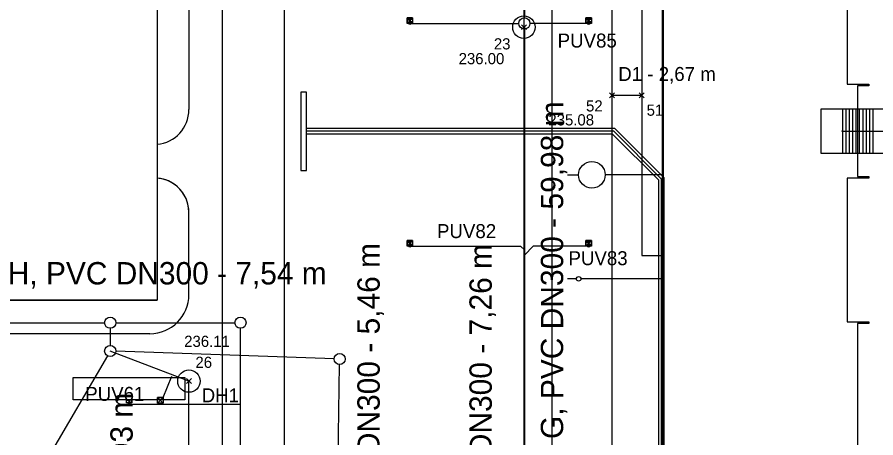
# Model space of a CAD drawing. Extents: x -264234 to -263604, y -1242346 to -1242049.
# Drawn here: x -263972 to -263895.1, y -1242191.8 to -1242154.2 of the extents above; entities that cross this region are included whole.
import ezdxf

# ---------------------------------------------------------------- set-up
doc = ezdxf.new("R2010")
doc.units = 0
for name, color, linetype in [('KFA_BODY_CISLO', 7, 'Continuous'), ('KFA_BODY_SYMBOL', 7, 'Continuous'), ('KFA_BODY_VYSKA', 7, 'Continuous'), ('KFA_DAZDOVA_KANALIZACIA_pripojky_tA_tC', 7, 'Continuous'), ('KFA_DAZDOVA_KANALIZACIA_pripojky_tA_tC_popis', 7, 'Continuous'), ('KFA_DAZDOVA_KANALIZACIA_vetva_G', 7, 'Continuous'), ('KFA_DAZDOVA_KANALIZACIA_vetva_G_popis', 7, 'Continuous'), ('KFA_DAZDOVA_KANALIZACIA_vetva_H', 7, 'Continuous'), ('KFA_DAZDOVA_KANALIZACIA_vetva_H_popis', 7, 'Continuous'), ('KFA_JESTV_IS_DSP_-_KANAL_DAZD', 7, 'Continuous'), ('KFA_SITUACIA_DSP', 7, 'Continuous'), ('KFA_SO_40-2-II_DK_PRIPOJKY_UV_PROJEKT', 7, 'Continuous'), ('KFA_SO_40-2-II_DK_PRIPOJKY_UV_PROJEKT_popis', 7, 'Continuous'), ('KFA_SO_40-2-II_DK_UV_PROJEKT', 7, 'Continuous')]:
    doc.layers.add(name, color=color, linetype=linetype)

msp = doc.modelspace()

# ---------------------------------------------------------------- linework, layer by layer
at = {"layer": 'KFA_BODY_SYMBOL'}
for p, q in [((-263926.86, -1242155.303), (-263926.418, -1242154.861)), ((-263926.418, -1242155.303), (-263926.86, -1242154.861)), ((-263918.984, -1242161.403), (-263918.542, -1242160.961)), ((-263918.542, -1242161.403), (-263918.984, -1242160.961)), ((-263916.314, -1242161.403), (-263915.872, -1242160.961)), ((-263915.872, -1242161.403), (-263916.314, -1242160.961)), ((-263956.837, -1242186.94), (-263956.395, -1242186.498)), ((-263956.395, -1242186.94), (-263956.837, -1242186.498))]:
    msp.add_line(p, q, dxfattribs=at)
at = {"layer": 'KFA_DAZDOVA_KANALIZACIA_pripojky_tA_tC'}
msp.add_line((-263916.093, -1242161.182), (-263918.763, -1242161.182), dxfattribs=at)
at = {"layer": 'KFA_DAZDOVA_KANALIZACIA_vetva_G'}
msp.add_lwpolyline([(-263926.523, -1242108.42), (-263926.639, -1242155.082), (-263926.646, -1242205.066)], dxfattribs=at)
msp.add_circle((-263926.639, -1242155.082), 1, dxfattribs=at)
at = {"layer": 'KFA_DAZDOVA_KANALIZACIA_vetva_H'}
msp.add_lwpolyline([(-263956.104, -1242251.541), (-263956.553, -1242222.652), (-263956.616, -1242186.719), (-263963.661, -1242184.028)], dxfattribs=at)
msp.add_circle((-263956.616, -1242186.719), 1, dxfattribs=at)
at = {"layer": 'KFA_JESTV_IS_DSP_-_KANAL_DAZD'}
for p, q in [((-263918.764, -1242152.564), (-263918.757, -1242196.225)), ((-263943.628, -1242184.728), (-263963.161, -1242184.046)), ((-263963.914, -1242184.46), (-263969.615, -1242194.201)), ((-263943.946, -1242236.311), (-263943.136, -1242185.245))]:
    msp.add_line(p, q, dxfattribs=at)
for centre in [(-263963.661, -1242184.028), (-263943.128, -1242184.745)]:
    msp.add_circle(centre, 0.5, dxfattribs=at)
at = {"layer": 'KFA_SITUACIA_DSP'}
for p, q in [((-263959.468, -1242059.534), (-263959.468, -1242179.482)), ((-263924.143, -1242082.64), (-263924.143, -1242185.14)), ((-263948.093, -1242087.901), (-263948.093, -1242241.458)), ((-263953.617, -1242244.458), (-263953.617, -1242093.307)), ((-263926.593, -1242107.902), (-263926.593, -1242154.252)), ((-263926.593, -1242107.902), (-263926.593, -1242154.252)), ((-263956.618, -1242127.418), (-263956.618, -1242162.449)), ((-263914.218, -1242196.332), (-263914.218, -1242132.432)), ((-263897.693, -1242147.332), (-263897.693, -1242160.182)), ((-263937.093, -1242154.652), (-263937.093, -1242154.362)), ((-263937.093, -1242154.362), (-263936.593, -1242154.362)), ((-263936.593, -1242154.652), (-263937.093, -1242154.362)), ((-263936.593, -1242154.652), (-263937.093, -1242154.362)), ((-263937.093, -1242154.362), (-263937.093, -1242154.652)), ((-263936.593, -1242154.652), (-263937.093, -1242154.652)), ((-263937.093, -1242154.652), (-263936.593, -1242154.652)), ((-263936.743, -1242154.752), (-263927.093, -1242154.752)), ((-263936.593, -1242154.362), (-263936.593, -1242154.652)), ((-263920.944, -1242154.752), (-263926.093, -1242154.752)), ((-263921.093, -1242154.652), (-263921.093, -1242154.362)), ((-263921.093, -1242154.362), (-263920.593, -1242154.362)), ((-263920.593, -1242154.652), (-263921.093, -1242154.362)), ((-263920.593, -1242154.652), (-263921.093, -1242154.362)), ((-263921.093, -1242154.362), (-263921.093, -1242154.652)), ((-263920.593, -1242154.652), (-263921.093, -1242154.652)), ((-263921.093, -1242154.652), (-263920.593, -1242154.652)), ((-263920.593, -1242154.362), (-263920.593, -1242154.652)), ((-263926.593, -1242155.252), (-263926.593, -1242204.252)), ((-263897.693, -1242160.182), (-263895.768, -1242160.182)), ((-263895.768, -1242160.332), (-263896.768, -1242160.332)), ((-263896.768, -1242160.332), (-263896.768, -1242168.432)), ((-263895.768, -1242160.182), (-263895.768, -1242160.332)), ((-263916.093, -1242161.182), (-263918.763, -1242161.182)), ((-263898.118, -1242162.382), (-263898.118, -1242166.382)), ((-263897.818, -1242162.382), (-263897.818, -1242166.382)), ((-263897.518, -1242162.382), (-263897.518, -1242166.382)), ((-263897.218, -1242162.382), (-263897.218, -1242166.382)), ((-263896.918, -1242162.382), (-263896.918, -1242166.382)), ((-263896.618, -1242162.382), (-263896.618, -1242166.382)), ((-263896.318, -1242162.382), (-263896.318, -1242166.382)), ((-263896.018, -1242162.382), (-263896.018, -1242166.382)), ((-263895.718, -1242162.382), (-263895.718, -1242166.382)), ((-263895.418, -1242162.382), (-263895.418, -1242166.382)), ((-263918.489, -1242164.132), (-263946.093, -1242164.132)), ((-263918.593, -1242164.382), (-263946.093, -1242164.382)), ((-263918.696, -1242164.632), (-263946.093, -1242164.632)), ((-263898.118, -1242164.382), (-263893.618, -1242164.382)), ((-263959.468, -1242165.549), (-263959.468, -1242165.549)), ((-263959.467, -1242168.582), (-263959.467, -1242168.582)), ((-263922.745, -1242168.282), (-263921.745, -1242168.282)), ((-263914.143, -1242168.282), (-263919.355, -1242168.282)), ((-263895.768, -1242168.582), (-263897.693, -1242168.582)), ((-263897.693, -1242168.582), (-263897.693, -1242181.432)), ((-263896.768, -1242168.432), (-263895.768, -1242168.432)), ((-263895.768, -1242168.432), (-263895.768, -1242168.582)), ((-263956.618, -1242178.982), (-263956.618, -1242171.645)), ((-263937.093, -1242174.553), (-263937.093, -1242174.263)), ((-263937.093, -1242174.263), (-263936.593, -1242174.263)), ((-263936.593, -1242174.553), (-263937.093, -1242174.263)), ((-263936.593, -1242174.553), (-263937.093, -1242174.263)), ((-263937.093, -1242174.263), (-263937.093, -1242174.553)), ((-263936.593, -1242174.553), (-263937.093, -1242174.553)), ((-263937.093, -1242174.553), (-263936.593, -1242174.553)), ((-263936.743, -1242174.653), (-263926.953, -1242174.653)), ((-263936.593, -1242174.263), (-263936.593, -1242174.553)), ((-263926.953, -1242174.653), (-263926.593, -1242174.978)), ((-263925.798, -1242174.653), (-263926.593, -1242175.448)), ((-263920.944, -1242174.653), (-263925.798, -1242174.653)), ((-263921.093, -1242174.553), (-263921.093, -1242174.263)), ((-263921.093, -1242174.263), (-263920.593, -1242174.263)), ((-263920.593, -1242174.553), (-263921.093, -1242174.263)), ((-263920.593, -1242174.553), (-263921.093, -1242174.263)), ((-263921.093, -1242174.263), (-263921.093, -1242174.553)), ((-263920.593, -1242174.553), (-263921.093, -1242174.553)), ((-263921.093, -1242174.553), (-263920.593, -1242174.553)), ((-263920.593, -1242174.263), (-263920.593, -1242174.553)), ((-263921.938, -1242177.582), (-263922.738, -1242177.582)), ((-263915.293, -1242177.582), (-263921.538, -1242177.582)), ((-263914.143, -1242177.582), (-263915.293, -1242177.582)), ((-264131.568, -1242179.482), (-263959.468, -1242179.482)), ((-263959.468, -1242179.482), (-264131.568, -1242179.482)), ((-263959.468, -1242179.482), (-264077.23, -1242179.482)), ((-263956.618, -1242178.982), (-263956.618, -1242178.982)), ((-264013.161, -1242181.5), (-263964.161, -1242181.5)), ((-263963.161, -1242181.5), (-263952.5, -1242181.5)), ((-263897.693, -1242181.432), (-263895.768, -1242181.432)), ((-263895.768, -1242181.582), (-263896.768, -1242181.582)), ((-263896.768, -1242181.582), (-263896.768, -1242203.332)), ((-263895.768, -1242181.432), (-263895.768, -1242181.582)), ((-263960.118, -1242182.482), (-264034.158, -1242182.482)), ((-263963.661, -1242182), (-263963.661, -1242183.528)), ((-263952, -1242222.527), (-263952, -1242182)), ((-263924.143, -1242185.14), (-263924.143, -1242250.14)), ((-263962.218, -1242188.382), (-263961.718, -1242188.382)), ((-263962.218, -1242188.672), (-263962.218, -1242188.382)), ((-263962.218, -1242188.382), (-263961.718, -1242188.672)), ((-263962.218, -1242188.382), (-263961.718, -1242188.672)), ((-263961.718, -1242188.382), (-263962.218, -1242188.382)), ((-263961.718, -1242188.672), (-263962.218, -1242188.672)), ((-263961.718, -1242188.382), (-263961.718, -1242188.672)), ((-263961.718, -1242188.672), (-263961.718, -1242188.382)), ((-263961.868, -1242188.772), (-263952, -1242188.772))]:
    msp.add_line(p, q, dxfattribs=at)
for points in [[(-263794.893, -1242227.382), (-263808.968, -1242241.457), (-263894.968, -1242241.457), (-263909.043, -1242227.382), (-263909.043, -1242196.333), (-263914.143, -1242196.333), (-263914.143, -1242132.433), (-263909.043, -1242132.433), (-263909.043, -1242101.382), (-263894.968, -1242087.307), (-263808.968, -1242087.307), (-263794.893, -1242101.382), (-263794.893, -1242227.382)], [(-263918.489, -1242164.132), (-263914.1, -1242168.521), (-263914.1, -1242199.486), (-263910.004, -1242203.582), (-263891.768, -1242203.582)], [(-263918.696, -1242164.632), (-263914.6, -1242168.728), (-263914.6, -1242199.693), (-263910.211, -1242204.082), (-263891.768, -1242204.082)], [(-263918.593, -1242164.382), (-263914.35, -1242168.625), (-263914.35, -1242199.59), (-263910.108, -1242203.832), (-263891.768, -1242203.832)], [(-263956.618, -1242178.982), (-263956.618, -1242171.626), (-263956.64, -1242171.257), (-263956.707, -1242170.894), (-263956.87, -1242170.411), (-263957.158, -1242169.893), (-263957.435, -1242169.549), (-263957.705, -1242169.291), (-263958.077, -1242169.024), (-263958.45, -1242168.829), (-263958.842, -1242168.69), (-263959.056, -1242168.638), (-263959.273, -1242168.601), (-263959.468, -1242168.582)]]:
    msp.add_lwpolyline(points, dxfattribs=at)
for points in [[(-263893.618, -1242118.282), (-263916.093, -1242118.282), (-263916.093, -1242175.482), (-263914.293, -1242175.482), (-263914.293, -1242210.482), (-263893.618, -1242210.482), (-263893.618, -1242166.382), (-263900.043, -1242166.382), (-263900.043, -1242162.382), (-263893.618, -1242162.382)], [(-263946.093, -1242167.882), (-263946.093, -1242160.882), (-263946.593, -1242160.882), (-263946.593, -1242167.882)], [(-263966.968, -1242186.382), (-263956.968, -1242186.382), (-263956.968, -1242188.382), (-263966.968, -1242188.382)]]:
    msp.add_lwpolyline(points, close=True, dxfattribs=at)
for centre, radius in [((-263936.843, -1242154.752), 0.1), ((-263926.593, -1242154.752), 0.5), ((-263920.844, -1242154.752), 0.1), ((-263898.118, -1242164.382), 0.05), ((-263920.55, -1242168.282), 1.195), ((-263936.843, -1242174.653), 0.1), ((-263920.844, -1242174.653), 0.1), ((-263921.738, -1242177.582), 0.2), ((-263963.661, -1242181.5), 0.5), ((-263952, -1242181.5), 0.5), ((-263961.968, -1242188.772), 0.1)]:
    msp.add_circle(centre, radius, dxfattribs=at)
for centre, radius, start, end in [((-263959.738, -1242162.441), 3.12, 274.96374, 359.8482), ((-263959.668, -1242171.626), 3.05, 359.64411, 86.21555), ((-263960.118, -1242178.982), 3.5, 270, 0)]:
    msp.add_arc(centre, radius, start, end, dxfattribs=at)
at = {"layer": 'KFA_SO_40-2-II_DK_PRIPOJKY_UV_PROJEKT'}
for points in [[(-263936.743, -1242154.752), (-263927.093, -1242154.752)], [(-263920.944, -1242154.752), (-263926.093, -1242154.752)], [(-263936.743, -1242174.653), (-263926.953, -1242174.653), (-263926.593, -1242174.978)], [(-263920.944, -1242174.653), (-263925.798, -1242174.653), (-263926.593, -1242175.448)], [(-263958.93, -1242188.19), (-263958.149, -1242186.27)]]:
    msp.add_lwpolyline(points, dxfattribs=at)
at = {"layer": 'KFA_SO_40-2-II_DK_UV_PROJEKT'}
for points in [[(-263937.093, -1242154.757), (-263937.093, -1242154.257), (-263936.593, -1242154.257), (-263936.593, -1242154.757), (-263937.093, -1242154.757), (-263936.593, -1242154.257), (-263937.093, -1242154.257), (-263936.593, -1242154.757)], [(-263921.093, -1242154.757), (-263921.093, -1242154.257), (-263920.593, -1242154.257), (-263920.593, -1242154.757), (-263921.093, -1242154.757), (-263920.593, -1242154.257), (-263921.093, -1242154.257), (-263920.593, -1242154.757)], [(-263937.093, -1242174.658), (-263937.093, -1242174.158), (-263936.593, -1242174.158), (-263936.593, -1242174.658), (-263937.093, -1242174.658), (-263936.593, -1242174.158), (-263937.093, -1242174.158), (-263936.593, -1242174.658)], [(-263921.093, -1242174.658), (-263921.093, -1242174.158), (-263920.593, -1242174.158), (-263920.593, -1242174.658), (-263921.093, -1242174.658), (-263920.593, -1242174.158), (-263921.093, -1242174.158), (-263920.593, -1242174.658)], [(-263959.43, -1242188.69), (-263959.43, -1242188.19), (-263958.93, -1242188.19), (-263958.93, -1242188.69), (-263959.43, -1242188.69), (-263958.93, -1242188.19), (-263959.43, -1242188.19), (-263958.93, -1242188.69)]]:
    msp.add_lwpolyline(points, dxfattribs=at)

# ---------------------------------------------------------------- texts
at = {"layer": 'KFA_BODY_CISLO'}
for s, p in [('23', (-263929.324, -1242157.075)), ('52', (-263921.077, -1242162.619)), ('51', (-263915.653, -1242163.002)), ('26', (-263956.034, -1242185.539))]:
    msp.add_text(s, height=1, dxfattribs=at).set_placement(p)
at = {"layer": 'KFA_BODY_VYSKA'}
for s, p in [('236.00', (-263932.48, -1242158.395)), ('235.08', (-263924.447, -1242163.868)), ('236.11', (-263957.04, -1242183.663))]:
    msp.add_text(s, height=1, dxfattribs=at).set_placement(p)
at = {"layer": 'KFA_DAZDOVA_KANALIZACIA_pripojky_tA_tC_popis'}
msp.add_text('D1 - 2,67 m', height=1.25, dxfattribs=at).set_placement((-263918.194, -1242159.893))
at = {"layer": 'KFA_DAZDOVA_KANALIZACIA_vetva_G_popis'}
for s, p in [('G, PVC DN300 - 59,98 m', (-263923.121, -1242191.895)), ('G, PVC DN300 - 5,46 m', (-263939.541, -1242203.058)), ('G, PVC DN300 - 7,26 m', (-263929.511, -1242203.15))]:
    msp.add_text(s, height=2, rotation=90, dxfattribs=at).set_placement(p)
at = {"layer": 'KFA_DAZDOVA_KANALIZACIA_vetva_H_popis'}
for s, rotation, p in [('H, PVC DN300 - 7,54 m', 360, (-263972.826, -1242178.078)), ('H, PVC DN300 - 35,93 m', 90, (-263961.646, -1242217.779))]:
    msp.add_text(s, height=2, rotation=rotation, dxfattribs=at).set_placement(p)
msp.add_text('DH1', height=1.25, dxfattribs=at).set_placement((-263955.474, -1242188.614))
at = {"layer": 'KFA_SO_40-2-II_DK_PRIPOJKY_UV_PROJEKT_popis'}
for s, p in [('PUV85', (-263923.618, -1242156.905)), ('PUV82', (-263934.417, -1242173.937)), ('PUV83', (-263922.647, -1242176.357)), ('PUV61', (-263965.898, -1242188.484))]:
    msp.add_text(s, height=1.25, dxfattribs=at).set_placement(p)

doc.saveas('drawing.dxf')
